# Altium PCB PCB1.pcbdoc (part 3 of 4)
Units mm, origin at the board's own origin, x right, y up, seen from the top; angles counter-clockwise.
Board outline 94.87 x 122.3 mm, 4 copper layers (Top Layer, Inner1, Inner2, Bottom Layer); 129 components, 127 nets, 714 pads, 326 vias.
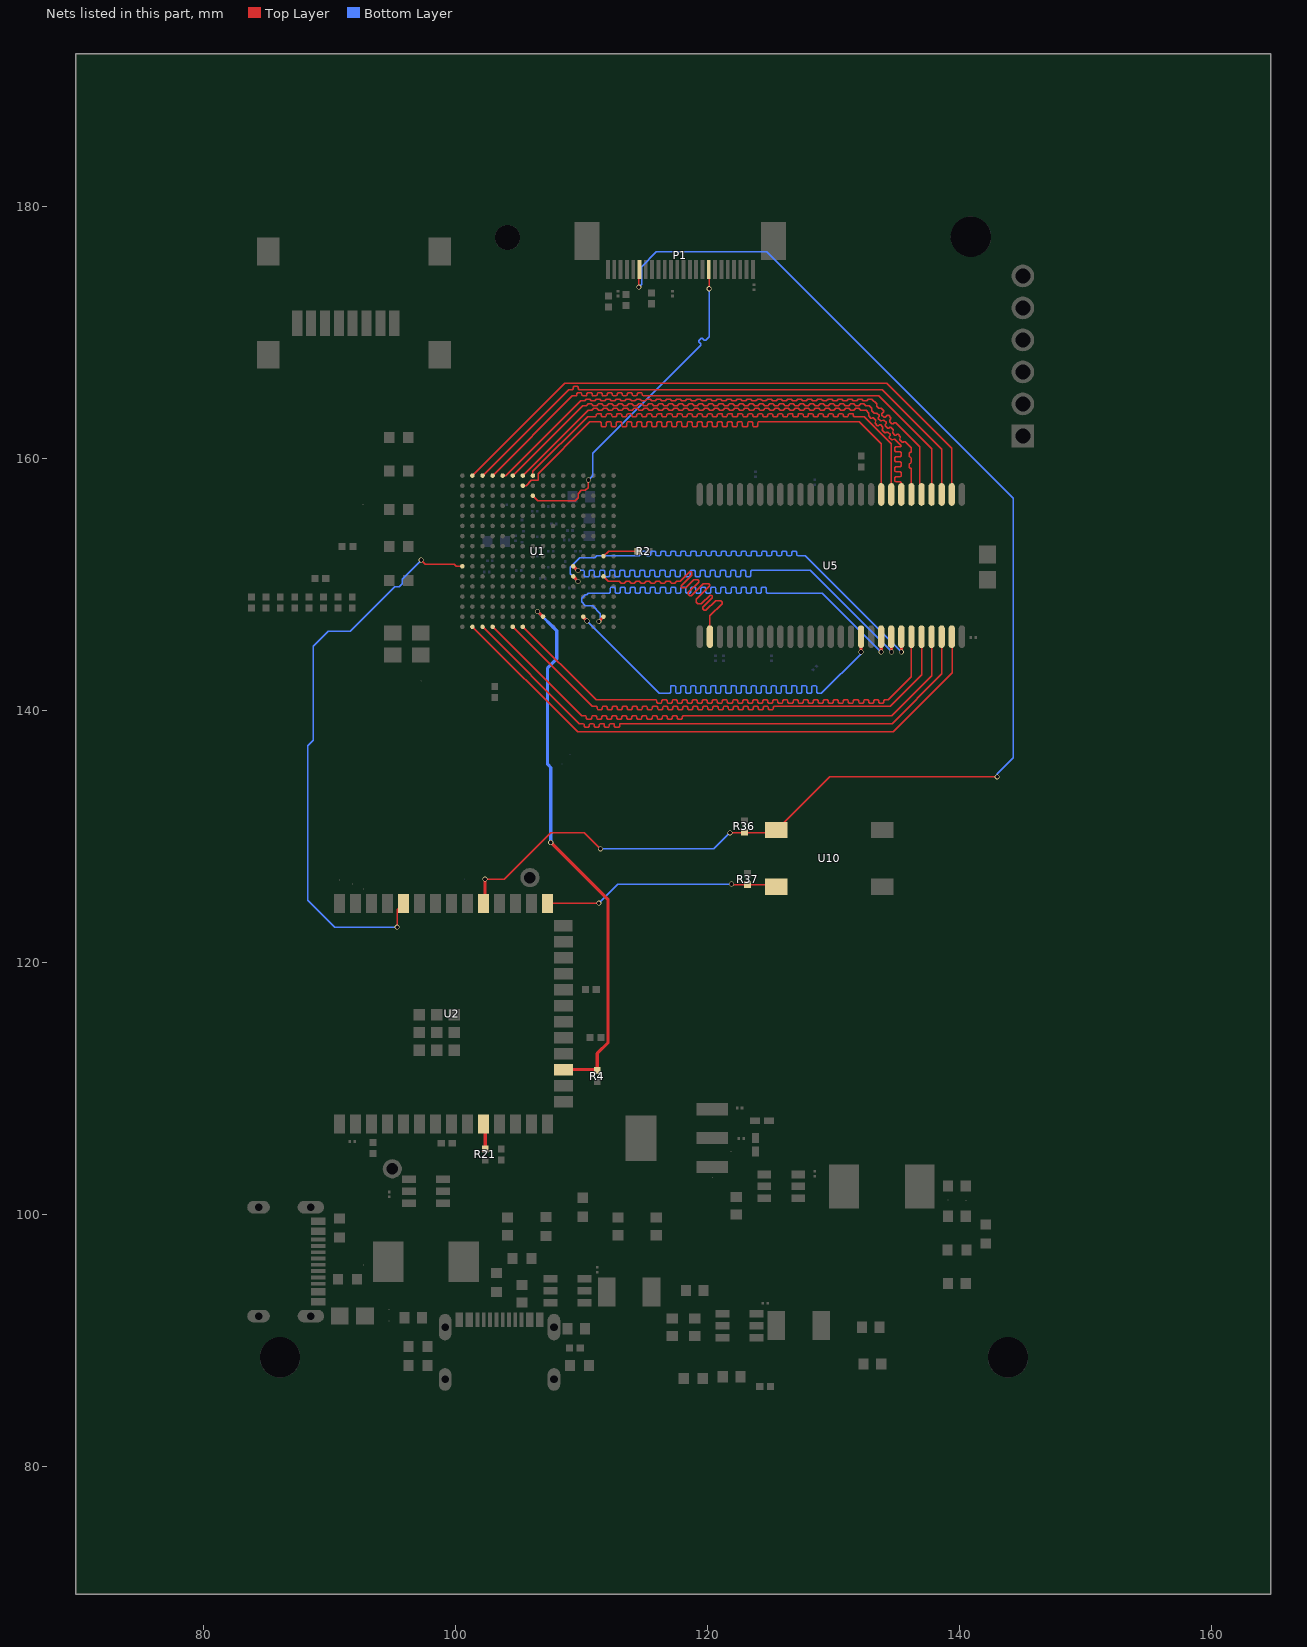
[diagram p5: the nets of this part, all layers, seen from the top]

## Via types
v1: diameter 0.4, hole 0.3, Top Layer to Bottom Layer, 311 vias
v2: diameter 1, hole 0.5, Top Layer to Bottom Layer, 12 vias
v3: diameter 0.5, hole 0.3, Top Layer to Bottom Layer, 3 vias

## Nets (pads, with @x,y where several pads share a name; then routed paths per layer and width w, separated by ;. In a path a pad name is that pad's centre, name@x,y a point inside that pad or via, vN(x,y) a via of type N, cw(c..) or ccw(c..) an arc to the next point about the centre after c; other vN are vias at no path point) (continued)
PCLK: P1.17 U1.C8 | length 27
  Top Layer w0.1: U1.C8@106.153,157.054 106.535,156.672 109.511,156.672 109.735,156.896 109.735,157.212 109.995,157.472 110.311,157.472 110.535,157.696 110.535,158.012 110.553,158.03 v1(110.553,158.302) ; P1.17@120.11,175.021 120.142,174.989 v1(120.142,173.482)
  Bottom Layer w0.1: v1(110.553,158.302) 110.892,158.641 110.892,160.422 119.482,169.012 119.482,169.112 119.328,169.266 119.328,169.366 119.51,169.548 119.61,169.548 119.764,169.394 119.864,169.394 120.142,169.672 v1(120.142,173.482)
PROGRAM: R37.1 U2.27 U10.3 | length 18.9
  Top Layer w0.1: U2.27@107.31,124.701 111.366,124.701 v1(111.379,124.714) ; v1(121.92,126.238) 121.972,126.186 R37.1@123.19,126.186 125.301,126.186 U10.3@125.467,126.02
  Bottom Layer w0.1: v1(111.379,124.714) 112.903,126.238 v1(121.92,126.238)
PROGRAMN: pad.55@107.315,135.742 R4.2 U1.R9 U2.17 | length 42.9
  Top Layer w0.254: v1(106.516,147.865) 106.542,147.865 U1.R9@106.953,147.454 ; v1(107.569,129.54) 112.12,124.989 112.12,113.66 111.252,112.793 R4.2@111.252,111.431 111.177,111.506 U2.17@108.717,111.506
  Bottom Layer w0.254: v1(106.516,147.865) 108.048,146.333 108.048,144.123 107.315,143.39 pad.55@107.315,135.742 107.569,135.488 v1(107.569,129.54)
RESET: P1.6 R36.1 U2.31 U10.1 | length 110.8
  Top Layer w0.1: v1(102.357,126.619) 103.886,126.619 107.569,130.302 110.236,130.302 v1(111.506,129.032) ; v1(114.554,173.609) 114.554,174.964 P1.6@114.611,175.02 ; v1(121.793,130.302) 125.249,130.302 U10.1@125.467,130.52 129.694,134.747 v1(143.002,134.747)
  Top Layer w0.254: U2.31@102.357,124.701 v1(102.357,126.619)
  Bottom Layer w0.1: v1(111.506,129.032) 120.523,129.032 v1(121.793,130.302) ; v1(114.554,173.609) 114.78,173.835 114.78,175.232 115.951,176.403 124.714,176.403 144.272,156.845 144.272,136.271 143.002,135.001 v1(143.002,134.747)
RX: U1.K1 U2.36 | length 45.5
  Top Layer w0.1: v1(95.377,122.809) 95.377,124.198 U2.36@95.88,124.701 ; v1(97.283,151.947) 97.611,151.619 99.91,151.619 100.075,151.454 U1.K1@100.553,151.454
  Bottom Layer w0.1: v1(95.377,122.809) 90.424,122.809 88.265,124.968 88.265,137.196 88.705,137.636 88.705,145.093 89.916,146.304 91.64,146.304 95.175,149.839 95.544,149.839 95.779,150.074 95.779,150.443 v1(97.283,151.947)
SCL: R21.1 U2.10 | length 1.9
  Top Layer w0.254: U2.10@102.357,107.201 102.362,107.196 R21.1@102.362,105.283
SD_A0: U1.T6 U5.23 | length 45.3
  Top Layer w0.1: U1.T6@104.553,146.654 110.872,140.335 111.172,140.335 111.243,140.264 111.243,140.152 111.313,140.081 111.572,140.081 111.643,140.152 111.643,140.264 111.713,140.335 111.972,140.335 112.043,140.264 112.043,140.152 112.113,140.081 112.372,140.081 112.443,140.152 112.443,140.264 112.513,140.335 112.772,140.335 112.843,140.264 112.843,140.152 112.913,140.081 113.172,140.081 113.243,140.152 113.243,140.264 113.313,140.335 113.572,140.335 113.643,140.264 113.643,140.152 113.713,140.081 113.972,140.081 114.043,140.152 114.043,140.264 114.113,140.335 114.372,140.335 114.443,140.264 114.443,140.152 114.513,140.081 114.772,140.081 114.843,140.152 114.843,140.264 114.913,140.335 115.172,140.335 115.243,140.264 115.243,140.152 115.313,140.081 115.572,140.081 115.643,140.152 115.643,140.264 115.713,140.335 115.972,140.335 116.043,140.264 116.043,140.152 116.113,140.081 116.372,140.081 116.443,140.152 116.443,140.264 116.513,140.335 116.772,140.335 116.843,140.264 116.843,140.152 116.913,140.081 117.172,140.081 117.243,140.152 117.243,140.264 117.313,140.335 117.572,140.335 117.643,140.264 117.643,140.152 117.713,140.081 117.972,140.081 118.043,140.152 118.043,140.264 118.113,140.335 118.372,140.335 118.443,140.264 118.443,140.152 118.513,140.081 118.772,140.081 118.843,140.152 118.843,140.264 118.913,140.335 119.172,140.335 119.243,140.264 119.243,140.152 119.313,140.081 119.572,140.081 119.643,140.152 119.643,140.264 119.713,140.335 119.972,140.335 120.043,140.264 120.043,140.152 120.113,140.081 120.372,140.081 120.443,140.152 120.443,140.264 120.513,140.335 120.772,140.335 120.843,140.264 120.843,140.152 120.913,140.081 121.172,140.081 121.243,140.152 121.243,140.264 121.313,140.335 121.572,140.335 121.643,140.264 121.643,140.152 121.713,140.081 121.972,140.081 122.043,140.152 122.043,140.264 122.113,140.335 122.372,140.335 122.443,140.264 122.443,140.152 122.513,140.081 122.772,140.081 122.843,140.152 122.843,140.264 122.913,140.335 123.172,140.335 123.243,140.264 123.243,140.152 123.313,140.081 123.572,140.081 123.643,140.152 123.643,140.264 123.713,140.335 123.972,140.335 124.043,140.264 124.043,140.152 124.113,140.081 124.372,140.081 124.443,140.152 124.443,140.264 124.513,140.335 124.772,140.335 124.843,140.264 124.843,140.152 124.913,140.081 125.172,140.081 125.243,140.152 125.243,140.264 125.313,140.335 134.493,140.335 136.994,142.836 U5.23@136.994,145.869
SD_A1: U1.T4 U5.24 | length 45.6
  Top Layer w0.1: U1.T4@102.953,146.654 110.034,139.573 110.334,139.573 110.405,139.502 110.405,139.39 110.475,139.319 110.734,139.319 110.805,139.39 110.805,139.502 110.875,139.573 111.134,139.573 111.205,139.502 111.205,139.39 111.275,139.319 111.534,139.319 111.605,139.39 111.605,139.502 111.675,139.573 111.934,139.573 112.005,139.502 112.005,139.39 112.075,139.319 112.334,139.319 112.405,139.39 112.405,139.502 112.475,139.573 112.734,139.573 112.805,139.502 112.805,139.39 112.875,139.319 113.134,139.319 113.205,139.39 113.205,139.502 113.275,139.573 113.534,139.573 113.605,139.502 113.605,139.39 113.675,139.319 113.934,139.319 114.005,139.39 114.005,139.502 114.075,139.573 114.334,139.573 114.405,139.502 114.405,139.39 114.475,139.319 114.734,139.319 114.805,139.39 114.805,139.502 114.875,139.573 115.134,139.573 115.205,139.502 115.205,139.39 115.275,139.319 115.534,139.319 115.605,139.39 115.605,139.502 115.675,139.573 115.934,139.573 116.005,139.502 116.005,139.39 116.075,139.319 116.334,139.319 116.405,139.39 116.405,139.502 116.475,139.573 116.734,139.573 116.805,139.502 116.805,139.39 116.875,139.319 117.134,139.319 117.205,139.39 117.205,139.502 117.275,139.573 117.534,139.573 117.605,139.502 117.605,139.39 117.675,139.319 117.934,139.319 118.005,139.39 118.005,139.502 118.075,139.573 134.62,139.573 137.795,142.748 U5.24@137.795,145.868
SD_A2: U1.T3 U5.25 | length 45.9
  Top Layer w0.1: U1.T3@102.153,146.654 109.832,138.975 110.155,138.975 110.226,138.904 110.226,138.755 110.296,138.684 110.555,138.684 110.626,138.755 110.626,138.904 110.696,138.975 110.955,138.975 111.026,138.904 111.026,138.755 111.096,138.684 111.355,138.684 111.426,138.755 111.426,138.904 111.496,138.975 111.755,138.975 111.826,138.904 111.826,138.755 111.896,138.684 112.155,138.684 112.226,138.755 112.226,138.904 112.296,138.975 112.555,138.975 112.626,138.904 112.626,138.755 112.696,138.684 112.955,138.684 113.026,138.755 113.026,138.904 113.096,138.975 134.657,138.975 138.594,142.912 U5.25@138.594,145.869
SD_A3: U1.T2 U5.26 | length 46.4
  Top Layer w0.1: U1.T2@101.353,146.654 109.704,138.303 134.747,138.303 139.446,143.002 139.446,145.817 U5.26@139.394,145.869
SD_A4: U1.A2 U5.29 | length 46.9
  Top Layer w0.1: U1.A2@101.353,158.654 108.688,165.989 134.239,165.989 139.394,160.834 U5.29@139.394,157.153
SD_A5: U1.A3 U5.30 | length 45.2
  Top Layer w0.1: U1.A3@102.153,158.654 108.98,165.481 109.28,165.481 109.351,165.552 109.351,165.664 109.421,165.735 109.68,165.735 109.751,165.664 109.751,165.552 109.821,165.481 133.858,165.481 138.594,160.745 U5.30@138.594,157.153
SD_A6: U1.A4 U5.31 | length 45.2
  Top Layer w0.1: U1.A4@102.953,158.654 109.272,164.973 109.572,164.973 109.643,165.044 109.643,165.156 109.713,165.227 109.972,165.227 110.043,165.156 110.043,165.044 110.113,164.973 110.372,164.973 110.443,165.044 110.443,165.156 110.513,165.227 110.772,165.227 110.843,165.156 110.843,165.044 110.913,164.973 111.172,164.973 111.243,165.044 111.243,165.156 111.313,165.227 111.572,165.227 111.643,165.156 111.643,165.044 111.713,164.973 111.972,164.973 112.043,165.044 112.043,165.156 112.113,165.227 112.372,165.227 112.443,165.156 112.443,165.044 112.513,164.973 112.772,164.973 112.843,165.044 112.843,165.156 112.913,165.227 113.172,165.227 113.243,165.156 113.243,165.044 113.313,164.973 113.572,164.973 113.643,165.044 113.643,165.156 113.713,165.227 113.972,165.227 114.043,165.156 114.043,165.044 114.113,164.973 114.372,164.973 114.443,165.044 114.443,165.156 114.513,165.227 114.772,165.227 114.843,165.156 114.843,165.044 114.913,164.973 133.604,164.973 137.794,160.783 U5.31@137.794,157.153
SD_A7: U1.A5 U5.32 | length 45.1
  Top Layer w0.1: U1.A5@103.753,158.654 104.013,158.654 109.951,164.592 110.251,164.592 110.378,164.719 110.651,164.719 110.778,164.592 111.051,164.592 111.178,164.719 111.451,164.719 111.578,164.592 111.851,164.592 111.978,164.719 112.251,164.719 112.378,164.592 112.651,164.592 112.778,164.719 113.051,164.719 113.178,164.592 113.451,164.592 113.578,164.719 113.851,164.719 113.978,164.592 114.251,164.592 114.378,164.719 114.651,164.719 114.778,164.592 115.051,164.592 115.178,164.719 115.451,164.719 115.578,164.592 115.851,164.592 115.978,164.719 116.251,164.719 116.378,164.592 116.651,164.592 116.778,164.719 117.051,164.719 117.178,164.592 117.451,164.592 117.578,164.719 117.851,164.719 117.978,164.592 118.251,164.592 118.378,164.719 118.651,164.719 118.778,164.592 119.051,164.592 119.178,164.719 119.451,164.719 119.578,164.592 119.851,164.592 119.978,164.719 120.251,164.719 120.378,164.592 120.651,164.592 120.778,164.719 121.051,164.719 121.178,164.592 121.451,164.592 121.578,164.719 121.851,164.719 121.978,164.592 122.251,164.592 122.378,164.719 122.651,164.719 122.778,164.592 123.051,164.592 123.178,164.719 123.451,164.719 123.578,164.592 123.851,164.592 123.978,164.719 124.251,164.719 124.378,164.592 124.651,164.592 124.778,164.719 125.051,164.719 125.178,164.592 125.451,164.592 125.578,164.719 125.851,164.719 125.978,164.592 126.251,164.592 126.378,164.719 126.651,164.719 126.778,164.592 127.051,164.592 127.178,164.719 127.451,164.719 127.578,164.592 127.851,164.592 127.978,164.719 128.251,164.719 128.378,164.592 128.651,164.592 128.778,164.719 129.051,164.719 129.178,164.592 129.451,164.592 129.578,164.719 129.851,164.719 129.978,164.592 130.251,164.592 130.378,164.719 130.651,164.719 130.778,164.592 131.051,164.592 131.178,164.719 131.451,164.719 131.578,164.592 131.851,164.592 131.978,164.719 132.251,164.719 132.378,164.592 132.651,164.592 132.778,164.719 133.051,164.719 133.423,164.347 133.423,164.168 133.606,163.985 133.706,163.985 133.718,163.997 133.818,163.997 134.001,163.814 134.001,163.714 133.847,163.56 133.847,163.46 134.029,163.277 134.129,163.277 134.284,163.431 134.384,163.431 134.567,163.248 134.567,163.148 134.461,163.043 134.461,162.943 134.644,162.76 134.744,162.76 134.849,162.866 134.949,162.866 136.867,160.948 136.867,157.28 U5.32@136.994,157.153
SD_A8: U1.A6 U5.33 | length 44.4
  Top Layer w0.1: U1.A6@104.553,158.654 110.11,164.211 110.41,164.211 110.481,164.282 110.481,164.292 110.551,164.363 110.81,164.363 110.881,164.292 110.881,164.282 110.951,164.211 111.21,164.211 111.281,164.282 111.281,164.292 111.351,164.363 111.61,164.363 111.681,164.292 111.681,164.282 111.751,164.211 112.01,164.211 112.081,164.282 112.081,164.292 112.151,164.363 112.41,164.363 112.481,164.292 112.481,164.282 112.551,164.211 112.81,164.211 112.881,164.282 112.881,164.292 112.951,164.363 113.21,164.363 113.281,164.292 113.281,164.282 113.351,164.211 113.61,164.211 113.681,164.282 113.681,164.292 113.751,164.363 114.01,164.363 114.081,164.292 114.081,164.282 114.151,164.211 114.41,164.211 114.481,164.282 114.481,164.292 114.551,164.363 114.81,164.363 114.881,164.292 114.881,164.282 114.951,164.211 115.21,164.211 115.281,164.282 115.281,164.292 115.351,164.363 115.61,164.363 115.681,164.292 115.681,164.282 115.751,164.211 116.01,164.211 116.081,164.282 116.081,164.292 116.151,164.363 116.41,164.363 116.481,164.292 116.481,164.282 116.551,164.211 116.81,164.211 116.881,164.282 116.881,164.292 116.951,164.363 117.21,164.363 117.281,164.292 117.281,164.282 117.351,164.211 117.61,164.211 117.681,164.282 117.681,164.292 117.751,164.363 118.01,164.363 118.081,164.292 118.081,164.282 118.151,164.211 118.41,164.211 118.481,164.282 118.481,164.292 118.551,164.363 118.81,164.363 118.881,164.292 118.881,164.282 118.951,164.211 119.21,164.211 119.281,164.282 119.281,164.292 119.351,164.363 119.61,164.363 119.681,164.292 119.681,164.282 119.751,164.211 120.01,164.211 120.081,164.282 120.081,164.292 120.151,164.363 120.41,164.363 120.481,164.292 120.481,164.282 120.551,164.211 120.81,164.211 120.881,164.282 120.881,164.292 120.951,164.363 121.21,164.363 121.281,164.292 121.281,164.282 121.351,164.211 121.61,164.211 121.681,164.282 121.681,164.292 121.751,164.363 122.01,164.363 122.081,164.292 122.081,164.282 122.151,164.211 122.41,164.211 122.481,164.282 122.481,164.292 122.551,164.363 122.81,164.363 122.881,164.292 122.881,164.282 122.951,164.211 123.21,164.211 123.281,164.282 123.281,164.292 123.351,164.363 123.61,164.363 123.681,164.292 123.681,164.282 123.751,164.211 124.01,164.211 124.081,164.282 124.081,164.292 124.151,164.363 124.41,164.363 124.481,164.292 124.481,164.282 124.551,164.211 124.81,164.211 124.881,164.282 124.881,164.292 124.951,164.363 125.21,164.363 125.281,164.292 125.281,164.282 125.351,164.211 125.61,164.211 125.681,164.282 125.681,164.292 125.751,164.363 126.01,164.363 126.081,164.292 126.081,164.282 126.151,164.211 126.41,164.211 126.481,164.282 126.481,164.292 126.551,164.363 126.81,164.363 126.881,164.292 126.881,164.282 126.951,164.211 127.21,164.211 127.281,164.282 127.281,164.292 127.351,164.363 127.61,164.363 127.681,164.292 127.681,164.282 127.751,164.211 128.01,164.211 128.081,164.282 128.081,164.292 128.151,164.363 128.41,164.363 128.481,164.292 128.481,164.282 128.551,164.211 128.81,164.211 128.881,164.282 128.881,164.292 128.951,164.363 129.21,164.363 129.281,164.292 129.281,164.282 129.351,164.211 129.61,164.211 129.681,164.282 129.681,164.292 129.751,164.363 130.01,164.363 130.081,164.292 130.081,164.282 130.151,164.211 130.41,164.211 130.481,164.282 130.481,164.292 130.551,164.363 130.81,164.363 130.881,164.292 130.881,164.282 130.951,164.211 131.21,164.211 131.281,164.282 131.281,164.292 131.351,164.363 131.61,164.363 131.681,164.292 131.681,164.282 131.751,164.211 132.01,164.211 132.081,164.282 132.081,164.292 132.151,164.363 132.41,164.363 132.481,164.292 132.481,164.282 132.551,164.211 132.842,164.211 133.054,163.999 133.054,163.899 133.042,163.887 133.042,163.787 133.225,163.604 133.325,163.604 133.337,163.616 133.437,163.616 133.62,163.433 133.62,163.333 133.564,163.278 133.564,163.178 133.747,162.995 133.847,162.995 133.903,163.05 134.003,163.05 134.186,162.867 134.186,162.767 134.13,162.712 134.13,162.612 134.313,162.429 134.413,162.429 134.468,162.485 134.568,162.485 134.751,162.302 134.751,162.202 134.696,162.146 134.696,162.046 134.879,161.864 134.979,161.864 135.034,161.919 135.134,161.919 135.317,161.736 135.317,161.636 135.27,161.59 135.27,161.49 135.453,161.307 135.553,161.307 135.6,161.353 135.7,161.353 136.194,160.859 136.194,160.559 136.123,160.488 136.106,160.488 136.035,160.418 136.035,160.159 136.106,160.088 136.123,160.088 136.194,160.018 136.194,159.718 136.123,159.647 136.106,159.647 136.035,159.576 136.035,159.318 136.106,159.247 136.123,159.247 136.194,159.176 U5.33@136.194,157.153
SD_A9: U1.A7 U5.34 | length 45.4
  Top Layer w0.1: U1.A7@105.353,158.654 110.529,163.83 110.829,163.83 110.9,163.901 110.9,163.911 110.971,163.982 111.229,163.982 111.3,163.911 111.3,163.901 111.371,163.83 111.629,163.83 111.7,163.901 111.7,163.911 111.771,163.982 112.029,163.982 112.1,163.911 112.1,163.901 112.171,163.83 112.429,163.83 112.5,163.901 112.5,163.911 112.571,163.982 112.829,163.982 112.9,163.911 112.9,163.901 112.971,163.83 113.229,163.83 113.3,163.901 113.3,163.911 113.371,163.982 113.629,163.982 113.7,163.911 113.7,163.901 113.771,163.83 114.029,163.83 114.1,163.901 114.1,163.911 114.171,163.982 114.429,163.982 114.5,163.911 114.5,163.901 114.571,163.83 114.829,163.83 114.9,163.901 114.9,163.911 114.971,163.982 115.229,163.982 115.3,163.911 115.3,163.901 115.371,163.83 115.629,163.83 115.7,163.901 115.7,163.911 115.771,163.982 116.029,163.982 116.1,163.911 116.1,163.901 116.171,163.83 116.429,163.83 116.5,163.901 116.5,163.911 116.571,163.982 116.829,163.982 116.9,163.911 116.9,163.901 116.971,163.83 117.229,163.83 117.3,163.901 117.3,163.911 117.371,163.982 117.629,163.982 117.7,163.911 117.7,163.901 117.771,163.83 118.029,163.83 118.1,163.901 118.1,163.911 118.171,163.982 118.429,163.982 118.5,163.911 118.5,163.901 118.571,163.83 118.829,163.83 118.9,163.901 118.9,163.911 118.971,163.982 119.229,163.982 119.3,163.911 119.3,163.901 119.371,163.83 119.629,163.83 119.7,163.901 119.7,163.911 119.771,163.982 120.029,163.982 120.1,163.911 120.1,163.901 120.171,163.83 120.429,163.83 120.5,163.901 120.5,163.911 120.571,163.982 120.829,163.982 120.9,163.911 120.9,163.901 120.971,163.83 121.229,163.83 121.3,163.901 121.3,163.911 121.371,163.982 121.629,163.982 121.7,163.911 121.7,163.901 121.771,163.83 122.029,163.83 122.1,163.901 122.1,163.911 122.171,163.982 122.429,163.982 122.5,163.911 122.5,163.901 122.571,163.83 122.829,163.83 122.9,163.901 122.9,163.911 122.971,163.982 123.229,163.982 123.3,163.911 123.3,163.901 123.371,163.83 123.629,163.83 123.7,163.901 123.7,163.911 123.771,163.982 124.029,163.982 124.1,163.911 124.1,163.901 124.171,163.83 124.429,163.83 124.5,163.901 124.5,163.911 124.571,163.982 124.829,163.982 124.9,163.911 124.9,163.901 124.971,163.83 125.229,163.83 125.3,163.901 125.3,163.911 125.371,163.982 125.629,163.982 125.7,163.911 125.7,163.901 125.771,163.83 126.029,163.83 126.1,163.901 126.1,163.911 126.171,163.982 126.429,163.982 126.5,163.911 126.5,163.901 126.571,163.83 126.829,163.83 126.9,163.901 126.9,163.911 126.971,163.982 127.229,163.982 127.3,163.911 127.3,163.901 127.371,163.83 127.629,163.83 127.7,163.901 127.7,163.911 127.771,163.982 128.029,163.982 128.1,163.911 128.1,163.901 128.171,163.83 128.429,163.83 128.5,163.901 128.5,163.911 128.571,163.982 128.829,163.982 128.9,163.911 128.9,163.901 128.971,163.83 129.229,163.83 129.3,163.901 129.3,163.911 129.371,163.982 129.629,163.982 129.7,163.911 129.7,163.901 129.771,163.83 130.029,163.83 130.1,163.901 130.1,163.911 130.171,163.982 130.429,163.982 130.5,163.911 130.5,163.901 130.571,163.83 130.829,163.83 130.9,163.901 130.9,163.911 130.971,163.982 131.229,163.982 131.3,163.911 131.3,163.901 131.371,163.83 131.629,163.83 131.7,163.901 131.7,163.911 131.771,163.982 132.029,163.982 132.1,163.911 132.1,163.901 132.171,163.83 132.588,163.83 132.8,163.618 132.8,163.518 132.788,163.506 132.788,163.406 132.971,163.223 133.071,163.223 133.083,163.235 133.183,163.235 133.366,163.052 133.366,162.952 133.31,162.897 133.31,162.797 133.493,162.614 133.593,162.614 133.649,162.669 133.749,162.669 133.932,162.486 133.932,162.386 133.876,162.331 133.876,162.231 134.059,162.048 134.159,162.048 134.214,162.104 134.314,162.104 134.497,161.921 134.497,161.821 134.442,161.765 134.442,161.665 134.625,161.483 134.725,161.483 134.78,161.538 134.88,161.538 135.394,161.024 135.394,161.016 135.323,160.945 134.945,160.945 134.874,160.875 134.874,160.616 134.945,160.545 135.323,160.545 135.394,160.475 135.394,160.216 135.323,160.145 134.945,160.145 134.874,160.075 134.874,159.816 134.945,159.745 135.323,159.745 135.394,159.675 135.394,159.416 135.323,159.345 134.945,159.345 134.874,159.275 134.874,159.016 134.945,158.945 135.323,158.945 135.394,158.875 135.394,158.616 135.323,158.545 134.945,158.545 134.874,158.475 134.874,158.216 134.945,158.145 135.323,158.145 135.394,158.075 U5.34@135.394,157.153
SD_A10: U1.T7 U5.22 | length 45.1
  Top Layer w0.1: U1.T7@105.353,146.654 111.164,140.843 115.925,140.843 115.995,140.772 115.995,140.66 116.066,140.589 116.325,140.589 116.395,140.66 116.395,140.772 116.466,140.843 116.725,140.843 116.795,140.772 116.795,140.66 116.866,140.589 117.125,140.589 117.195,140.66 117.195,140.772 117.266,140.843 117.525,140.843 117.595,140.772 117.595,140.66 117.666,140.589 117.925,140.589 117.995,140.66 117.995,140.772 118.066,140.843 118.325,140.843 118.395,140.772 118.395,140.66 118.466,140.589 118.725,140.589 118.795,140.66 118.795,140.772 118.866,140.843 119.125,140.843 119.195,140.772 119.195,140.66 119.266,140.589 119.525,140.589 119.595,140.66 119.595,140.772 119.666,140.843 119.925,140.843 119.995,140.772 119.995,140.66 120.066,140.589 120.325,140.589 120.395,140.66 120.395,140.772 120.466,140.843 120.725,140.843 120.795,140.772 120.795,140.66 120.866,140.589 121.125,140.589 121.195,140.66 121.195,140.772 121.266,140.843 121.525,140.843 121.595,140.772 121.595,140.66 121.666,140.589 121.925,140.589 121.995,140.66 121.995,140.772 122.066,140.843 122.325,140.843 122.395,140.772 122.395,140.66 122.466,140.589 122.725,140.589 122.795,140.66 122.795,140.772 122.866,140.843 123.125,140.843 123.195,140.772 123.195,140.66 123.266,140.589 123.525,140.589 123.595,140.66 123.595,140.772 123.666,140.843 123.925,140.843 123.995,140.772 123.995,140.66 124.066,140.589 124.325,140.589 124.395,140.66 124.395,140.772 124.466,140.843 124.725,140.843 124.795,140.772 124.795,140.66 124.866,140.589 125.125,140.589 125.195,140.66 125.195,140.772 125.266,140.843 125.525,140.843 125.595,140.772 125.595,140.66 125.666,140.589 125.925,140.589 125.995,140.66 125.995,140.772 126.066,140.843 126.325,140.843 126.395,140.772 126.395,140.66 126.466,140.589 126.725,140.589 126.795,140.66 126.795,140.772 126.866,140.843 127.125,140.843 127.195,140.772 127.195,140.66 127.266,140.589 127.525,140.589 127.595,140.66 127.595,140.772 127.666,140.843 127.925,140.843 127.995,140.772 127.995,140.66 128.066,140.589 128.325,140.589 128.395,140.66 128.395,140.772 128.466,140.843 128.725,140.843 128.795,140.772 128.795,140.66 128.866,140.589 129.125,140.589 129.195,140.66 129.195,140.772 129.266,140.843 129.525,140.843 129.595,140.772 129.595,140.66 129.666,140.589 129.925,140.589 129.995,140.66 129.995,140.772 130.066,140.843 130.325,140.843 130.395,140.772 130.395,140.66 130.466,140.589 130.725,140.589 130.795,140.66 130.795,140.772 130.866,140.843 131.125,140.843 131.195,140.772 131.195,140.66 131.266,140.589 131.525,140.589 131.595,140.66 131.595,140.772 131.666,140.843 131.925,140.843 131.995,140.772 131.995,140.66 132.066,140.589 132.325,140.589 132.395,140.66 132.395,140.772 132.466,140.843 132.725,140.843 132.795,140.772 132.795,140.66 132.866,140.589 133.125,140.589 133.195,140.66 133.195,140.772 133.266,140.843 133.525,140.843 133.595,140.772 133.595,140.66 133.666,140.589 133.925,140.589 133.995,140.66 133.995,140.772 134.066,140.843 134.366,140.843 136.194,142.671 U5.22@136.194,145.869
SD_A11: U1.A8 U5.35 | length 44.4
  Top Layer w0.1: U1.A8@106.153,158.654 106.153,158.985 110.49,163.322 111.121,163.322 111.192,163.393 111.192,163.505 111.262,163.576 111.521,163.576 111.592,163.505 111.592,163.393 111.662,163.322 111.921,163.322 111.992,163.393 111.992,163.505 112.062,163.576 112.321,163.576 112.392,163.505 112.392,163.393 112.462,163.322 112.721,163.322 112.792,163.393 112.792,163.505 112.862,163.576 113.121,163.576 113.192,163.505 113.192,163.393 113.262,163.322 113.521,163.322 113.592,163.393 113.592,163.505 113.662,163.576 113.921,163.576 113.992,163.505 113.992,163.393 114.062,163.322 114.321,163.322 114.392,163.393 114.392,163.505 114.462,163.576 114.721,163.576 114.792,163.505 114.792,163.393 114.862,163.322 115.121,163.322 115.192,163.393 115.192,163.505 115.262,163.576 115.521,163.576 115.592,163.505 115.592,163.393 115.662,163.322 115.921,163.322 115.992,163.393 115.992,163.505 116.062,163.576 116.321,163.576 116.392,163.505 116.392,163.393 116.462,163.322 116.721,163.322 116.792,163.393 116.792,163.505 116.862,163.576 117.121,163.576 117.192,163.505 117.192,163.393 117.262,163.322 117.521,163.322 117.592,163.393 117.592,163.505 117.662,163.576 117.921,163.576 117.992,163.505 117.992,163.393 118.062,163.322 118.321,163.322 118.392,163.393 118.392,163.505 118.462,163.576 118.721,163.576 118.792,163.505 118.792,163.393 118.862,163.322 119.121,163.322 119.192,163.393 119.192,163.505 119.262,163.576 119.521,163.576 119.592,163.505 119.592,163.393 119.662,163.322 119.921,163.322 119.992,163.393 119.992,163.505 120.062,163.576 120.321,163.576 120.392,163.505 120.392,163.393 120.462,163.322 120.721,163.322 120.792,163.393 120.792,163.505 120.862,163.576 121.121,163.576 121.192,163.505 121.192,163.393 121.262,163.322 121.521,163.322 121.592,163.393 121.592,163.505 121.662,163.576 121.921,163.576 121.992,163.505 121.992,163.393 122.062,163.322 122.321,163.322 122.392,163.393 122.392,163.505 122.462,163.576 122.721,163.576 122.792,163.505 122.792,163.393 122.862,163.322 123.121,163.322 123.192,163.393 123.192,163.505 123.262,163.576 123.521,163.576 123.592,163.505 123.592,163.393 123.662,163.322 123.921,163.322 123.992,163.393 123.992,163.505 124.062,163.576 124.321,163.576 124.392,163.505 124.392,163.393 124.462,163.322 124.721,163.322 124.792,163.393 124.792,163.505 124.862,163.576 125.121,163.576 125.192,163.505 125.192,163.393 125.262,163.322 125.521,163.322 125.592,163.393 125.592,163.505 125.662,163.576 125.921,163.576 125.992,163.505 125.992,163.393 126.062,163.322 126.321,163.322 126.392,163.393 126.392,163.505 126.462,163.576 126.721,163.576 126.792,163.505 126.792,163.393 126.862,163.322 127.121,163.322 127.192,163.393 127.192,163.505 127.262,163.576 127.521,163.576 127.592,163.505 127.592,163.393 127.662,163.322 127.921,163.322 127.992,163.393 127.992,163.505 128.062,163.576 128.321,163.576 128.392,163.505 128.392,163.393 128.462,163.322 128.721,163.322 128.792,163.393 128.792,163.505 128.862,163.576 129.121,163.576 129.192,163.505 129.192,163.393 129.262,163.322 129.521,163.322 129.592,163.393 129.592,163.505 129.662,163.576 129.921,163.576 129.992,163.505 129.992,163.393 130.062,163.322 130.321,163.322 130.392,163.393 130.392,163.505 130.462,163.576 130.721,163.576 130.792,163.505 130.792,163.393 130.862,163.322 131.121,163.322 131.192,163.393 131.192,163.505 131.262,163.576 131.521,163.576 131.592,163.505 131.592,163.393 131.662,163.322 132.461,163.322 134.594,161.189 U5.35@134.594,157.153
SD_A12: U1.B7 U5.36 | length 45.1
  Top Layer w0.1: U1.B7@105.353,157.854 105.613,157.854 106.031,158.272 106.546,158.272 106.571,158.297 106.571,158.812 110.673,162.914 111.513,162.914 111.584,162.843 111.584,162.604 111.654,162.533 111.913,162.533 111.984,162.604 111.984,162.843 112.054,162.914 112.313,162.914 112.384,162.843 112.384,162.604 112.454,162.533 112.713,162.533 112.784,162.604 112.784,162.843 112.854,162.914 113.113,162.914 113.184,162.843 113.184,162.604 113.254,162.533 113.513,162.533 113.584,162.604 113.584,162.843 113.654,162.914 113.913,162.914 113.984,162.843 113.984,162.604 114.054,162.533 114.313,162.533 114.384,162.604 114.384,162.843 114.454,162.914 114.713,162.914 114.784,162.843 114.784,162.604 114.854,162.533 115.113,162.533 115.184,162.604 115.184,162.843 115.254,162.914 115.513,162.914 115.584,162.843 115.584,162.604 115.654,162.533 115.913,162.533 115.984,162.604 115.984,162.843 116.054,162.914 116.313,162.914 116.384,162.843 116.384,162.604 116.454,162.533 116.713,162.533 116.784,162.604 116.784,162.843 116.854,162.914 117.113,162.914 117.184,162.843 117.184,162.604 117.254,162.533 117.513,162.533 117.584,162.604 117.584,162.843 117.654,162.914 117.913,162.914 117.984,162.843 117.984,162.604 118.054,162.533 118.313,162.533 118.384,162.604 118.384,162.843 118.454,162.914 118.713,162.914 118.784,162.843 118.784,162.604 118.854,162.533 119.113,162.533 119.184,162.604 119.184,162.843 119.254,162.914 119.513,162.914 119.584,162.843 119.584,162.604 119.654,162.533 119.913,162.533 119.984,162.604 119.984,162.843 120.054,162.914 120.313,162.914 120.384,162.843 120.384,162.604 120.454,162.533 120.713,162.533 120.784,162.604 120.784,162.843 120.854,162.914 121.113,162.914 121.184,162.843 121.184,162.604 121.254,162.533 121.513,162.533 121.584,162.604 121.584,162.843 121.654,162.914 121.913,162.914 121.984,162.843 121.984,162.604 122.054,162.533 122.313,162.533 122.384,162.604 122.384,162.843 122.454,162.914 122.713,162.914 122.784,162.843 122.784,162.604 122.854,162.533 123.113,162.533 123.184,162.604 123.184,162.843 123.254,162.914 123.513,162.914 123.584,162.843 123.584,162.604 123.654,162.533 123.913,162.533 123.984,162.604 123.984,162.843 124.054,162.914 132.053,162.914 133.794,161.173 U5.36@133.794,157.153
SD_BA0: U1.K12 U5.20 | length 43.4
  Top Layer w0.254: U1.K12@109.353,151.454 109.679,151.128 v1(109.726,151.128) ; U5.20@134.594,145.869 134.62,145.843 v1(134.62,144.653)
  Bottom Layer w0.1: v1(109.726,151.128) 110.167,151.128 110.238,151.058 110.238,150.702 110.309,150.631 110.567,150.631 110.638,150.702 110.638,151.058 110.709,151.128 110.967,151.128 111.038,151.058 111.038,150.702 111.109,150.631 111.367,150.631 111.438,150.702 111.438,151.058 111.509,151.128 111.767,151.128 111.838,151.058 111.838,150.702 111.909,150.631 112.167,150.631 112.238,150.702 112.238,151.058 112.309,151.128 112.567,151.128 112.638,151.058 112.638,150.702 112.709,150.631 112.967,150.631 113.038,150.702 113.038,151.058 113.109,151.128 113.367,151.128 113.438,151.058 113.438,150.702 113.509,150.631 113.767,150.631 113.838,150.702 113.838,151.058 113.909,151.128 114.167,151.128 114.238,151.058 114.238,150.702 114.309,150.631 114.567,150.631 114.638,150.702 114.638,151.058 114.709,151.128 114.967,151.128 115.038,151.058 115.038,150.702 115.109,150.631 115.367,150.631 115.438,150.702 115.438,151.058 115.509,151.128 115.767,151.128 115.838,151.058 115.838,150.702 115.909,150.631 116.167,150.631 116.238,150.702 116.238,151.058 116.309,151.128 116.567,151.128 116.638,151.058 116.638,150.702 116.709,150.631 116.967,150.631 117.038,150.702 117.038,151.058 117.109,151.128 117.367,151.128 117.438,151.058 117.438,150.702 117.509,150.631 117.767,150.631 117.838,150.702 117.838,151.058 117.909,151.128 118.167,151.128 118.238,151.058 118.238,150.702 118.309,150.631 118.567,150.631 118.638,150.702 118.638,151.058 118.709,151.128 118.967,151.128 119.038,151.058 119.038,150.702 119.109,150.631 119.367,150.631 119.438,150.702 119.438,151.058 119.509,151.128 119.767,151.128 119.838,151.058 119.838,150.702 119.909,150.631 120.167,150.631 120.238,150.702 120.238,151.058 120.309,151.128 120.567,151.128 120.638,151.058 120.638,150.702 120.709,150.631 120.967,150.631 121.038,150.702 121.038,151.058 121.109,151.128 121.367,151.128 121.438,151.058 121.438,150.702 121.509,150.631 121.767,150.631 121.838,150.702 121.838,151.058 121.909,151.128 122.167,151.128 122.238,151.058 122.238,150.702 122.309,150.631 122.567,150.631 122.638,150.702 122.638,151.058 122.709,151.128 122.967,151.128 123.038,151.058 123.038,150.702 123.109,150.631 123.367,150.631 123.438,150.702 123.438,151.058 123.509,151.128 128.145,151.128 v1(134.62,144.653)
SD_BA1: U1.L12 U5.21 | length 42.5
  Top Layer w0.254: U1.L12@109.353,150.654 109.728,150.279 v1(109.728,150.241) ; v1(135.394,144.653) U5.21@135.394,145.869
  Bottom Layer w0.1: v1(109.728,150.241) 109.124,150.845 109.124,151.378 109.865,152.118 111.057,152.118 111.212,152.273 114.627,152.273 114.698,152.344 114.698,152.583 114.769,152.654 115.027,152.654 115.098,152.583 115.098,152.344 115.169,152.273 115.427,152.273 115.498,152.344 115.498,152.583 115.569,152.654 115.827,152.654 115.898,152.583 115.898,152.344 115.969,152.273 116.227,152.273 116.298,152.344 116.298,152.583 116.369,152.654 116.627,152.654 116.698,152.583 116.698,152.344 116.769,152.273 117.027,152.273 117.098,152.344 117.098,152.583 117.169,152.654 117.427,152.654 117.498,152.583 117.498,152.344 117.569,152.273 117.827,152.273 117.898,152.344 117.898,152.583 117.969,152.654 118.227,152.654 118.298,152.583 118.298,152.344 118.369,152.273 118.627,152.273 118.698,152.344 118.698,152.583 118.769,152.654 119.027,152.654 119.098,152.583 119.098,152.344 119.169,152.273 119.427,152.273 119.498,152.344 119.498,152.583 119.569,152.654 119.827,152.654 119.898,152.583 119.898,152.344 119.969,152.273 120.227,152.273 120.298,152.344 120.298,152.583 120.369,152.654 120.627,152.654 120.698,152.583 120.698,152.344 120.769,152.273 121.027,152.273 121.098,152.344 121.098,152.583 121.169,152.654 121.427,152.654 121.498,152.583 121.498,152.344 121.569,152.273 121.827,152.273 121.898,152.344 121.898,152.583 121.969,152.654 122.227,152.654 122.298,152.583 122.298,152.344 122.369,152.273 122.627,152.273 122.698,152.344 122.698,152.583 122.769,152.654 123.027,152.654 123.098,152.583 123.098,152.344 123.169,152.273 123.427,152.273 123.498,152.344 123.498,152.583 123.569,152.654 123.827,152.654 123.898,152.583 123.898,152.344 123.969,152.273 124.227,152.273 124.298,152.344 124.298,152.583 124.369,152.654 124.627,152.654 124.698,152.583 124.698,152.344 124.769,152.273 125.027,152.273 125.098,152.344 125.098,152.583 125.169,152.654 125.427,152.654 125.498,152.583 125.498,152.344 125.569,152.273 125.827,152.273 125.898,152.344 125.898,152.583 125.969,152.654 126.227,152.654 126.298,152.583 126.298,152.344 126.369,152.273 126.627,152.273 126.698,152.344 126.698,152.583 126.769,152.654 127.027,152.654 127.098,152.583 127.098,152.344 127.169,152.273 127.774,152.273 v1(135.394,144.653)
SD_CAS_N: U1.R13 U5.17 | length 43.1
  Top Layer w0.254: U1.R13@110.153,147.454 110.153,147.406 v1(110.442,147.118) ; v1(132.194,144.653) U5.17@132.194,145.869
  Bottom Layer w0.1: v1(110.442,147.118) 116.185,141.374 117.005,141.374 117.076,141.445 117.076,141.915 117.146,141.986 117.405,141.986 117.476,141.915 117.476,141.445 117.546,141.374 117.805,141.374 117.876,141.445 117.876,141.915 117.946,141.986 118.205,141.986 118.276,141.915 118.276,141.445 118.346,141.374 118.605,141.374 118.676,141.445 118.676,141.915 118.746,141.986 119.005,141.986 119.076,141.915 119.076,141.445 119.146,141.374 119.405,141.374 119.476,141.445 119.476,141.915 119.546,141.986 119.805,141.986 119.876,141.915 119.876,141.445 119.946,141.374 120.205,141.374 120.276,141.445 120.276,141.915 120.346,141.986 120.605,141.986 120.676,141.915 120.676,141.445 120.746,141.374 121.005,141.374 121.076,141.445 121.076,141.915 121.146,141.986 121.405,141.986 121.476,141.915 121.476,141.445 121.546,141.374 121.805,141.374 121.876,141.445 121.876,141.915 121.946,141.986 122.205,141.986 122.276,141.915 122.276,141.445 122.346,141.374 122.605,141.374 122.676,141.445 122.676,141.915 122.746,141.986 123.005,141.986 123.076,141.915 123.076,141.445 123.146,141.374 123.405,141.374 123.476,141.445 123.476,141.915 123.546,141.986 123.805,141.986 123.876,141.915 123.876,141.445 123.946,141.374 124.205,141.374 124.276,141.445 124.276,141.915 124.346,141.986 124.605,141.986 124.676,141.915 124.676,141.445 124.746,141.374 125.005,141.374 125.076,141.445 125.076,141.915 125.146,141.986 125.405,141.986 125.476,141.915 125.476,141.445 125.546,141.374 125.805,141.374 125.876,141.445 125.876,141.915 125.946,141.986 126.205,141.986 126.276,141.915 126.276,141.445 126.346,141.374 126.605,141.374 126.676,141.445 126.676,141.915 126.746,141.986 127.005,141.986 127.076,141.915 127.076,141.445 127.146,141.374 127.405,141.374 127.476,141.445 127.476,141.915 127.546,141.986 127.805,141.986 127.876,141.915 127.876,141.445 127.946,141.374 128.205,141.374 128.276,141.445 128.276,141.915 128.346,141.986 128.605,141.986 128.676,141.915 128.676,141.445 128.746,141.374 129.046,141.374 132.194,144.522 v1(132.194,144.653)
SD_CLK: R2.2 U1.J15 | length 2.9
  Top Layer w0.1: U1.J15@111.753,152.254 112.153,152.654 R2.2@114.502,152.654
SD_CS_N: U1.R15 U5.19 | length 43
  Top Layer w0.254: v1(111.379,147.066) 111.753,147.44 U1.R15@111.753,147.454 ; v1(133.794,144.653) U5.19@133.794,145.869
  Bottom Layer w0.1: v1(111.379,147.066) 111.506,147.066 111.506,147.701 110.892,148.315 110.323,148.315 110.011,148.627 110.011,148.915 110.292,149.196 110.419,149.196 110.546,149.323 112.206,149.323 112.276,149.394 112.276,149.723 112.347,149.794 112.606,149.794 112.676,149.723 112.676,149.394 112.747,149.323 113.006,149.323 113.076,149.394 113.076,149.723 113.147,149.794 113.406,149.794 113.476,149.723 113.476,149.394 113.547,149.323 113.806,149.323 113.876,149.394 113.876,149.723 113.947,149.794 114.206,149.794 114.276,149.723 114.276,149.394 114.347,149.323 114.606,149.323 114.676,149.394 114.676,149.723 114.747,149.794 115.006,149.794 115.076,149.723 115.076,149.394 115.147,149.323 115.406,149.323 115.476,149.394 115.476,149.723 115.547,149.794 115.806,149.794 115.876,149.723 115.876,149.394 115.947,149.323 116.206,149.323 116.276,149.394 116.276,149.723 116.347,149.794 116.606,149.794 116.676,149.723 116.676,149.394 116.747,149.323 117.006,149.323 117.076,149.394 117.076,149.723 117.147,149.794 117.406,149.794 117.476,149.723 117.476,149.394 117.547,149.323 117.806,149.323 117.876,149.394 117.876,149.723 117.947,149.794 118.206,149.794 118.276,149.723 118.276,149.394 118.347,149.323 118.606,149.323 118.676,149.394 118.676,149.723 118.747,149.794 119.006,149.794 119.076,149.723 119.076,149.394 119.147,149.323 119.406,149.323 119.476,149.394 119.476,149.723 119.547,149.794 119.806,149.794 119.876,149.723 119.876,149.394 119.947,149.323 120.206,149.323 120.276,149.394 120.276,149.723 120.347,149.794 120.606,149.794 120.676,149.723 120.676,149.394 120.747,149.323 121.006,149.323 121.076,149.394 121.076,149.723 121.147,149.794 121.406,149.794 121.476,149.723 121.476,149.394 121.547,149.323 121.806,149.323 121.876,149.394 121.876,149.723 121.947,149.794 122.206,149.794 122.276,149.723 122.276,149.394 122.347,149.323 122.606,149.323 122.676,149.394 122.676,149.723 122.747,149.794 123.006,149.794 123.076,149.723 123.076,149.394 123.147,149.323 123.406,149.323 123.476,149.394 123.476,149.723 123.547,149.794 123.806,149.794 123.876,149.723 123.876,149.394 123.947,149.323 124.206,149.323 124.276,149.394 124.276,149.723 124.347,149.794 124.606,149.794 124.676,149.723 124.676,149.394 124.747,149.323 129.103,149.323 133.646,144.78 133.667,144.78 v1(133.794,144.653)
SD_DQ0: U1.L15 U5.2 | length 25
  Top Layer w0.1: U1.L15@111.753,150.654 112.135,150.272 113.002,150.272 113.073,150.201 113.073,150.185 113.143,150.114 113.402,150.114 113.473,150.185 113.473,150.201 113.543,150.272 113.802,150.272 113.873,150.201 113.873,150.185 113.943,150.114 114.202,150.114 114.273,150.185 114.273,150.201 114.343,150.272 114.602,150.272 114.673,150.201 114.673,150.185 114.743,150.114 115.002,150.114 115.073,150.185 115.073,150.201 115.143,150.272 115.402,150.272 115.473,150.201 115.473,150.185 115.543,150.114 115.802,150.114 115.873,150.185 115.873,150.201 115.943,150.272 116.202,150.272 116.273,150.201 116.273,150.185 116.343,150.114 116.602,150.114 116.673,150.185 116.673,150.201 116.743,150.272 117.002,150.272 117.073,150.201 117.073,150.185 117.143,150.114 117.402,150.114 117.473,150.185 117.473,150.201 117.543,150.272 117.843,150.272 118.604,151.032 118.716,151.032 118.745,151.003 118.745,150.749 117.922,149.926 117.922,149.794 117.983,149.733 118.284,149.733 118.919,150.368 119.228,150.368 119.299,150.297 119.299,150.197 118.491,149.389 118.491,149.225 118.618,149.098 118.709,149.098 119.668,150.058 120.123,150.058 120.194,149.987 120.194,149.893 119.126,148.825 119.126,148.59 119.253,148.463 119.507,148.463 120.213,149.169 120.325,149.169 120.396,149.098 120.396,148.946 119.634,148.184 119.634,148.082 119.761,147.955 119.888,147.955 120.65,148.717 121.048,148.717 121.168,148.596 121.168,148.496 120.194,147.522 U5.2@120.194,145.996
